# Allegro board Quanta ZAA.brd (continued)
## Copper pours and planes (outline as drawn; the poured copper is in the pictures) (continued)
VREF_CA_DIMM1 on TOP (solid shape): 117.94,64.41 118.05,64.37 118.17,64.36 118.17,60.47 118.02,60.32 117.99,60.32 117.98,60.32 117.53,60.2 117.53,59.74 117.53,59.57 117.45,59.34 117.53,59.1 117.53,58.3 117.45,58.07 117.53,57.83 117.53,57.66 117.46,57.53 117.46,57.38 117.45,57.35 117.44,57.33 117.4,57.3 117.02,57.3 116.9,57.42 116.9,59.96 117.28,60.34 117.28,62.63 117.15,62.76 117.15,63.42 117.18,63.53 117.19,63.65 117.19,63.9 117.4,64.11 117.4,64.4 117.4,64.41
N366230 on BOTTOM (solid shape): 224,109.52 224,108.9 224.26,108.64 224.58,108.64 224.6,108.62 224.6,107.14 223.77,106.31 223.77,105.69 223.46,105.39 222.16,105.39 222.09,105.45 222.09,106.52 222.18,106.61 222.42,106.63 222.61,106.78 223.15,106.78 223.73,107.12 223.13,107.42 223.1,107.4 222.88,107.62 222.88,109.51 223.07,109.71 223.81,109.71
N17047087 on TOP (solid shape): 176.64,178.33 176.64,174.39 174.17,171.93 166.86,171.93 166.85,171.91 166.69,171.91 165.24,170.46 165.23,170.46 165.05,170.35 164.95,170.18 164.94,170.16 163.9,169.13 163.8,169.1 163.73,169.18 163.72,169.25 163.69,169.33 163.7,169.43 163.8,169.47 164.15,170.24 163.5,169.7 163.49,169.59 163.39,169.56 162.88,169.2 163.26,168.7 163.34,168.63 163.31,168.53 161.25,166.47 158.93,166.47 158.86,166.54 158.86,166.95 158.65,167.15 158.4,167.15 157.99,167.56 157.99,170.05 158.58,170.63 158.58,171.19 161.47,174.09 161.47,175.94 162.88,177.35 169.75,177.35 170.48,178.07 171.41,178.07 171.94,178.61 176.36,178.61
N17047087 on BOTTOM (solid shape): 176.71,178.43 176.71,173.89 174.37,171.55 168.97,171.55 168.66,171.85 168.66,176.14 170.71,178.19 171.06,178.19 171.51,178.63 176.51,178.63
N17047087 on BOTTOM (solid shape): 157.48,170.81 160.42,170.81 160.71,170.52 160.71,167.23 160.51,167.02 157.89,167.02 157.84,167.08 157.36,167.08 156.8,167.63 155.68,167.63 155.58,167.74 155.58,168.92 155.63,169.11 155.58,169.3 155.58,170.94 155.68,171.04 157.26,171.04
N17047601 on TOP (solid shape): 157.82,168.57 157.82,167.2 158.02,167 158.53,167 158.63,166.9 158.63,166.54 158.48,166.39 157,166.39 156.85,166.54 156.85,168.52 156.97,168.64 157.75,168.64
N17047601 on BOTTOM (solid shape): 156.68,167.19 157.04,167.19 157.28,166.95 157.79,166.95 157.94,166.8 157.94,166.31 157.77,166.14 157.15,166.14 157.13,166.12 156.21,166.12 156.18,166.12 156.17,166.14 155.98,166.27 155.75,166.27 155.66,166.29 155.62,166.37 155.62,167.16 155.65,167.19 156.68,167.19
N17410561 on BOTTOM (solid shape): 58.48,96.41 58.48,94.76 58.73,94.51 58.73,90.65 58.45,90.37 54.08,90.37 54.06,90.34 53.42,90.34 53.09,90.67 53.09,93.24 52.51,93.82 52.51,96.67 52.76,96.92 57.97,96.92
N17410561 on BOTTOM (solid shape): 70.52,101.87 70.56,101.86 71.54,100.87 71.56,100.85 71.56,99.22 71.29,98.95 69.67,98.95 69.64,98.94 68.78,98.08 68.76,98.04 68.76,96.31 68.63,96.16 66.37,96.16 66.34,96.17 65.86,96.65 65.84,96.68 65.84,99.95 65.86,99.98 66.48,100.6 67.49,100.6 67.5,100.55 67.51,100.49 67.53,100.44 67.56,100.39 67.59,100.35 67.63,100.31 67.68,100.28 67.73,100.25 67.78,100.23 67.83,100.22 67.89,100.22 67.94,100.23 68,100.24 68.05,100.26 68.1,100.29 68.14,100.33 68.18,100.37 68.21,100.42 68.23,100.47 68.25,100.52 68.26,100.58 68.26,100.63 68.25,100.69 68.23,100.74 68.21,100.79 68.18,100.84 68.14,100.88 68.1,100.91 68.05,100.94 68,100.97 67.94,100.98 67.89,100.99 67.83,100.98 67.78,100.97 67.73,100.96 67.68,100.93 67.63,100.9 67.59,100.86 67.56,100.81 67.53,100.77 67.51,100.71 67.5,100.66 67.49,100.6 66.48,100.6 67.73,101.86 67.77,101.87
N17410561 on IN2 (solid shape): outline of 82 points within 54.03,94.43 70.34,101.24
N19011701 on BOTTOM (solid shape): 59.04,84.86 59.04,84.25 58.93,84.14 56.7,84.14 56.66,84.19 56.66,84.99 56.67,85.01 58.88,85.01
N19018012 on BOTTOM (solid shape): 133.95,115.57 133.97,115.56 134.08,115.49 134.18,115.47 134.21,115.47 134.44,115.24 134.48,115.24 134.66,115.05 134.75,115.05 134.78,115.04 134.79,115.02 134.86,114.93 134.96,114.86 135.04,114.83 135.14,114.83 135.18,114.82 135.23,114.79 135.24,114.77 135.24,114.74 135.23,114.65 135.26,114.56 135.27,114.53 135.27,114.4 135.42,114.24 135.44,114.23 135.44,114.17 135.45,114.1 135.45,113.91 135.44,113.88 135.36,113.83 134.96,113.83 134.95,113.84 134.83,113.87 134.72,113.84 134.71,113.83 134.31,113.83 134.3,113.84 134.18,113.87 134.07,113.84 134.05,113.83 133.92,113.83 133.67,114.08 133.67,114.41 133.68,114.43 133.69,114.45 133.8,114.65 133.73,114.85 133.72,114.87 133.71,114.89 133.71,114.93 133.67,114.96 133.67,115.5 133.75,115.57
N20965717 on BOTTOM (solid shape): 212.24,173.54 212.24,171.79 212.1,171.65 210.62,171.65 210.57,171.7 210.57,173.58 210.65,173.65 212.12,173.65
N21057151 on TOP (solid shape): 38.33,49.58 40.14,49.58 40.24,49.47 40.24,48.91 40.01,48.69 38.31,48.69 38.28,48.66 37.06,48.66 36.73,48.33 36.73,47.39 36.61,47.26 35.62,47.26 35.49,47.39 35.49,50.29 35.54,50.34 37.57,50.34
N21057157 on TOP (solid shape): 47.94,47.77 47.81,47.64 46.95,47.64 45.83,48.76 43.87,48.76 43.82,48.81 43.82,49.47 43.87,49.52 45.62,49.52 46.23,50.13 46.23,50.78 47.06,51.6 47.94,51.6
N21057413 on BOTTOM (solid shape): outline of 94 points within 156.29,69.21 161.35,74.16
N21854780 on BOTTOM (solid shape): 204.58,63.34 204.58,61.87 204.53,61.82 203.76,61.82 203.69,61.89 203.69,62.76 203.23,63.22 202.95,63.22 202.88,63.29 202.88,64.08 202.95,64.15 203.76,64.15
N21854999 on BOTTOM (solid shape): 196.75,64.15 196.75,63.34 196.63,63.22 196.42,63.22 195.97,62.76 195.97,61.95 195.87,61.84 195.03,61.84 195,61.87 195,63.27 195.92,64.18 196.73,64.18
N23587899 on TOP (solid shape): 51.52,43.96 51.52,43.2 51.42,43.1 50.96,43.1 50.73,42.87 50.73,41.75 50.63,41.65 49.84,41.65 49.74,41.75 49.74,43.2 50.63,44.09 51.39,44.09
N23588298 on TOP (solid shape): 50.43,35.5 50.43,34.69 50.76,34.36 51.09,34.36 51.14,34.31 51.14,33.52 51.06,33.45 50.25,33.45 49.49,34.21 49.49,35.5 49.54,35.55 50.37,35.55
N24001694 on BOTTOM (solid shape): 223.61,134.73 223.61,132.4 223.51,132.3 221.49,132.3 221.37,132.42 221.37,132.78 221.5,132.91 222.62,132.91 222.73,133.02 222.73,134.18 222.62,134.29 221.47,134.29 221.37,134.4 221.37,134.76 221.5,134.9 223.45,134.9
N25127202 on TOP (solid shape): 141.53,155.29 141.53,154.88 141.61,154.81 141.61,153.51 141.53,153.44 140.16,153.44 139.99,153.6 139.99,155.23 140.1,155.34 141.48,155.34
N25127289 on BOTTOM (solid shape): 132.35,164.68 132.35,163.93 132.23,163.8 130.13,163.8 130.13,163.8 130.1,163.83 129.15,163.83 129.13,163.84 129.12,163.85 129.08,163.89 129.07,163.9 129.06,163.92 129.06,164.72 129.07,164.74 129.08,164.75 129.12,164.8 129.14,164.81 129.16,164.82 132.22,164.82
N25127323 on BOTTOM (solid shape): 142.25,164.54 142.78,164.54 142.8,164.53 142.82,164.52 142.84,164.5 142.85,164.48 142.86,164.46 142.86,163.67 142.85,163.65 142.84,163.63 142.79,163.59 142.78,163.57 142.76,163.57 141.51,163.57 141.51,163.58 141.49,163.62 141.46,163.63 140.53,163.63 140.51,163.63 140.47,163.67 140.47,163.69 140.47,165.23 140.59,165.35 141.44,165.35
N25128837 on TOP (solid shape): 152.49,154.83 152.49,154.48 152.25,154.1 152.49,153.71 152.49,153.16 152.32,152.99 150.72,152.99 150.62,153.09 150.62,154.85 150.72,154.95 152.37,154.95
N25128839 on BOTTOM (solid shape): 153.96,165.14 153.96,163.74 153.95,163.72 153.94,163.71 153.87,163.64 153.85,163.63 153.83,163.62 152.56,163.62 152.56,163.63 152.54,163.67 152.51,163.68 151.53,163.68 151.51,163.69 151.49,163.7 151.46,163.73 151.44,163.75 151.44,163.77 151.44,165.21 151.55,165.32 153.78,165.32
N25168545 on BOTTOM (solid shape): 170.6,96.64 170.64,96.63 170.65,96.59 170.65,95.1 170.85,95.1 170.85,96.59 170.86,96.63 170.9,96.64 171.1,96.64 171.14,96.63 171.15,96.59 171.15,95.1 171.35,95.1 171.35,96.59 171.36,96.63 171.4,96.64 171.6,96.64 171.64,96.63 171.65,96.59 171.65,95.1 171.85,95.1 171.85,96.59 171.86,96.63 171.9,96.64 172.04,96.64 172.14,96.54 172.14,93.85 171.94,93.64 170.9,93.64 170.74,93.8 170.74,94.63 170.35,95.03 170.35,96.6 170.39,96.64
N26437442 on BOTTOM (solid shape): 171.45,50.25 171.45,48.1 171.36,48.02 170.92,48.02 170.84,48.1 170.84,50.34 170.92,50.42 171.28,50.42
N26437471 on BOTTOM (solid shape): 170.62,50.51 170.62,48.86 170.47,48.71 170.38,48.71 170.37,48.71 170.24,48.74 170.11,48.71 170.1,48.71 168.74,48.71 168.69,48.76 168.69,50.35 168.72,50.42 168.79,50.45 169.02,50.45 169.21,50.64 170.49,50.64
N26460931 on BOTTOM (solid shape): 68.52,78.46 68.82,78.46 70.18,77.1 70.18,76.28 70.14,76.23 68.55,76.23 68.52,76.26 68.52,77.07 67.96,77.63 67.96,78.43 68,78.47 68.51,78.47
N26462475 on TOP (solid shape): 48.49,61.1 48.49,60.3 48.45,60.25 47.08,60.25 46.41,59.58 46.1,59.58 46.02,59.66 46.02,60.11 46.15,60.24 46.15,61.1 46.19,61.14 48.45,61.14
N26464581 on TOP (solid shape): 221.59,174.25 221.59,172.87 221.51,172.79 218.96,172.79 218.75,172.99 218.75,173.63 219.55,174.43 221.41,174.43
N26464602 on BOTTOM (solid shape): 215.39,173.83 215.39,171.5 215.3,171.41 213.87,171.41 213.75,171.53 213.75,173.8 213.85,173.9 215.32,173.9
N27585563 on TOP (solid shape): 114.67,32 117.31,32 117.43,31.88 117.43,31.04 117.32,30.93 115.49,30.93 115.2,30.65 115.2,29.9 115.19,29.88 114.63,29.88 114.42,30.1 114.42,30.82 114.17,31.07 112.94,31.07 112.88,31.13 112.88,32.4 112.96,32.48 114.19,32.48
N281253841 on TOP (solid shape): 120.94,155.95 120.94,154.07 120.86,153.99 119.3,153.99 119.19,154.11 119.19,155.96 119.33,156.1 120.78,156.1
N281258110 on TOP (solid shape): 128.66,155.39 128.66,153.64 128.53,153.51 127.2,153.51 127.05,153.67 127.05,155.05 127.62,155.62 128.43,155.62

Small or netless copper shapes (teardrops, artwork), in the pictures only: 21 on TOP, 15 on BOTTOM, 179 on IN1, 7 on IN2

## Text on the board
Ref Des/Silkscreen Bottom: MODEL:ZAAA | DAZAAMB16E0 REV:E
User.Comments: 244.9 | 198.7 | 31.0x37.0 | 33.0x37.0
Ref Des/Silkscreen Top: DAZAAMB16E0 REV:E
User.12: GND | +3V_S5 | +5VPCU | +5V_S5 | +VCCCORE | +1V_S5 | +3VPCU | +3V3_TPM | +1.5V | ADOGND | +VCCSA | +VCCGT | +VGPU_CORE | VIN | +5V
User.27: GND | ADOGND
User.45: FIGURE | TYPE | Oblong | Circle | SIZE | 57.0x24.0 | 59.0x28.0 | 63.0x24.0 | 69.0x39.0 | 71.0x31.0 | 82.0x39.0 | 91.0x28.0 | 94.0x39.0 | 102.0x31.0 | 146.0x87.0 | 10.0 | 12.0 | 14.0 | 16.0 | 22.0 | 24.0 | 28.0 | 32.0 | 35.0 | 40.0 | 118.0 | 126.0 | 134.0 | 140.0 | 161.0 | 256.0 | 31.0 | 37.0 | 39.0 | 41.0 | 43.0 | 47.0 | 55.0 | 63.0 | 67.0 | 87.0 | 217.0 | DRILL CHART: TOP to BOTTOM | ALL UNITS ARE IN MILS | PLATED | NON-PLATED | ROTATION | 0.000 | 90.000 | - | QTY | 2 | 4 | 1 | 29 | 5223 | 37 | 1184 | 12 | 19 | 70 | 44 | 18 | 8 | 6 | 5 | 3 | 6660 | TOTAL HOLES:
